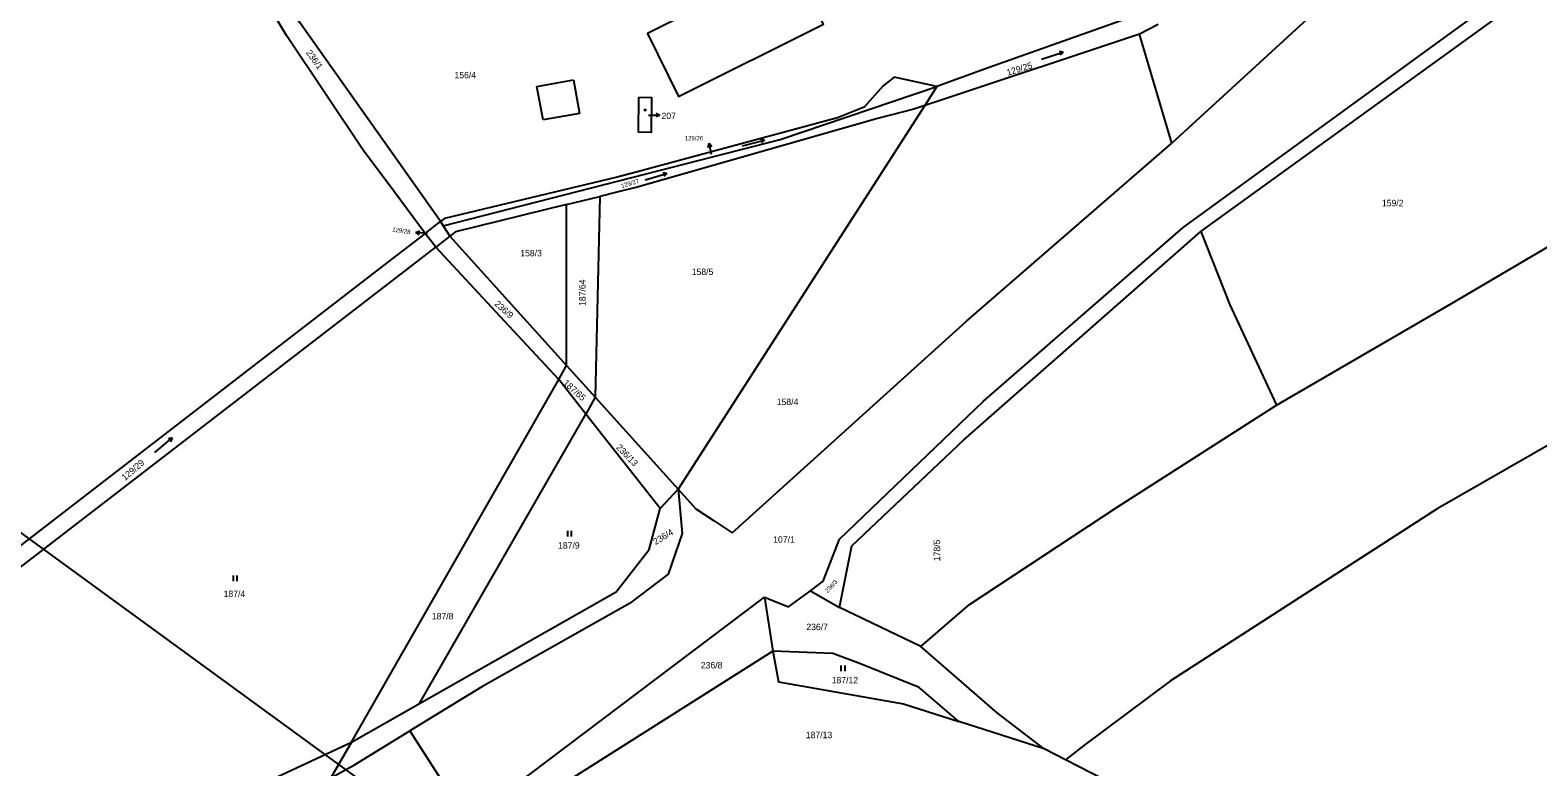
# Model space of a CAD drawing. Extents: x -670359 to -660124, y -978807 to -970072.
# Drawn here: x -662402 to -662004.8, y -971625.3 to -971431.1 of the extents above; entities that cross this region are included whole.
import ezdxf

# ---------------------------------------------------------------- set-up
doc = ezdxf.new("R2010")
doc.units = 0
for name, color, linetype in [('Hranice parcel', 7, 'Continuous'), ('Parcelní čísla', 7, 'Continuous'), ('Vnitřní kresba', 7, 'Continuous'), ('Značky budov', 7, 'Continuous'), ('Značky kultur', 7, 'Continuous')]:
    doc.layers.add(name, color=color, linetype=linetype)

# ---------------------------------------------------------------- blocks, each defined once
blk = doc.blocks.new('4.02')
at = {"layer": 'Značky budov'}
blk.add_circle((-0.01, 0), 0.175, dxfattribs=at)
blk = doc.blocks.new('8.02_4')
at = {"layer": 'Značky kultur'}
for p, q in [((-2.28, -1.92), (2.32, 1.93)), ((2.32, 1.93), (1.25, 1.69)), ((2.32, 1.93), (1.89, 0.92))]:
    blk.add_line(p, q, dxfattribs=at)
blk = doc.blocks.new('8.02_7')
at = {"layer": 'Značky kultur'}
for p, q in [((-2.83, -0.93), (2.87, 0.92)), ((2.87, 0.92), (1.79, 1.1)), ((2.87, 0.92), (2.1, 0.14))]:
    blk.add_line(p, q, dxfattribs=at)
blk = doc.blocks.new('8.02_12')
at = {"layer": 'Značky kultur'}
for p, q in [((-2.89, -0.73), (2.93, 0.72)), ((2.93, 0.72), (1.86, 0.97)), ((2.93, 0.72), (2.1, 0))]:
    blk.add_line(p, q, dxfattribs=at)
blk = doc.blocks.new('8.02_13')
at = {"layer": 'Značky kultur'}
for p, q in [((-2.86, -0.83), (2.9, 0.82)), ((2.9, 0.82), (1.82, 1.04)), ((2.9, 0.82), (2.1, 0.07))]:
    blk.add_line(p, q, dxfattribs=at)
blk = doc.blocks.new('1029_274')
at = {"layer": 'Parcelní čísla'}
for p, q in [((-0.5, 2), (0, 3)), ((0, 0), (0, 3)), ((0, 3), (0.5, 2))]:
    blk.add_line(p, q, dxfattribs=at)
blk = doc.blocks.new('3.06')
at = {"layer": 'Značky kultur'}
for p, q in [((-0.51, 0), (-0.51, 1.5)), ((0.49, 0), (0.49, 1.5))]:
    blk.add_line(p, q, dxfattribs=at)

msp = doc.modelspace()

# ---------------------------------------------------------------- linework, layer by layer
at = {"layer": 'Hranice parcel'}
for p, q in [((-664449.97, -970071.93), (-660124.07, -973226.54)), ((-662093.64, -971484.16), (-662006.91, -971421.5)), ((-662104.85, -971429.67), (-662109.78, -971432.21)), ((-662101.2, -971460.92), (-662109.78, -971432.21)), ((-662166.28, -971450.96), (-662231.31, -971552.12)), ((-662166.28, -971450.96), (-662169.24, -971451.94)), ((-662260.69, -971477.1), (-662289.92, -971484.3)), ((-662260.72, -971519.49), (-662260.69, -971477.1)), ((-662260.69, -971477.1), (-662251.9, -971474.94)), ((-662251.9, -971474.94), (-662253.16, -971527.88)), ((-662247.4, -971473.82), (-662251.9, -971474.94)), ((-662293.87, -971481.57), (-662294.28, -971481)), ((-662297.92, -971484.7), (-662293.87, -971481.57)), ((-662295.11, -971488.3), (-662297.92, -971484.7)), ((-662291.4, -971485.44), (-662295.11, -971488.3)), ((-662293.87, -971481.57), (-662293.17, -971482.67)), ((-662293.17, -971482.67), (-662291.4, -971485.44)), ((-662289.92, -971484.3), (-662291.4, -971485.44)), ((-662291.4, -971485.44), (-662260.72, -971519.49)), ((-662262.72, -971523.18), (-662260.72, -971519.49)), ((-662260.72, -971519.49), (-662253.16, -971527.88)), ((-662317.37, -971618.8), (-662262.72, -971523.18)), ((-662255.57, -971532.3), (-662262.72, -971523.18)), ((-662253.16, -971527.88), (-662255.57, -971532.3)), ((-662253.16, -971527.88), (-662231.31, -971552.12)), ((-662299.42, -971608.6), (-662255.57, -971532.3)), ((-662236.05, -971557.19), (-662255.57, -971532.3)), ((-662231.31, -971552.12), (-662236.05, -971557.19)), ((-662280.81, -971635.08), (-662208.55, -971580.53)), ((-662208.55, -971580.53), (-662206.34, -971594.76)), ((-662196.41, -971578.91), (-662188.74, -971583.27)), ((-662167.4, -971593.58), (-662188.74, -971583.27)), ((-662283.04, -971604.15), (-662302.01, -971615.82)), ((-662317.37, -971618.8), (-662299.42, -971608.6)), ((-662316.53, -971624.76), (-662302.01, -971615.82)), ((-662134.9, -971620.53), (-662157.38, -971613.31)), ((-662317.37, -971618.8), (-662322.78, -971628.13)), ((-662129.28, -971623.42), (-662134.9, -971620.53)), ((-662322.78, -971628.13), (-662316.53, -971624.76))]:
    msp.add_line(p, q, dxfattribs=at)
for points in [[(-661433.28, -971243.01), (-661557.59, -971305.11), (-661701.9, -971375.58), (-661831.06, -971446.31), (-661987.66, -971532.26), (-662031.35, -971557.26), (-662101.61, -971602.62), (-662124.46, -971619.63), (-662129.28, -971623.42)], [(-661822.45, -971261.99), (-661830.68, -971265.03), (-661863.68, -971280.61), (-661886.93, -971293.11), (-661912.11, -971308.3), (-661946.9, -971331.57), (-661983.27, -971359.52), (-662026.24, -971394.17), (-662057.15, -971420.41), (-662101.2, -971460.92)], [(-662196.41, -971578.91), (-662193.09, -971576.38), (-662188.82, -971565.31), (-662150.86, -971528.94), (-662098.27, -971483.13), (-662008, -971417.42), (-661977.36, -971384.36), (-661928.37, -971345.47), (-661860.63, -971297.88), (-661860.47, -971297.8)], [(-662294.28, -971481), (-662331.04, -971428.99), (-662343.81, -971404.49), (-662355.77, -971373.73), (-662379.27, -971301.66)], [(-662209.66, -971396.19), (-662237.17, -971409.99), (-662228.81, -971426.75), (-662239.4, -971432.04), (-662231.16, -971448.6), (-662192.99, -971429.55), (-662209.66, -971396.19)], [(-662297.92, -971484.7), (-662305.96, -971473.88), (-662314.27, -971462.71), (-662334.49, -971432.52), (-662342.84, -971418.45)], [(-662111.97, -971427.74), (-662149.37, -971440.94), (-662163.1, -971446.01)], [(-662109.78, -971432.21), (-662162.3, -971449.64), (-662166.28, -971450.96)], [(-662163.1, -971446.01), (-662174.34, -971443.55), (-662177.28, -971445.81), (-662182.3, -971451.38), (-662189.31, -971454.22), (-662242.31, -971468.56), (-662247.35, -971469.91), (-662292.81, -971480.76), (-662293.87, -971481.57)], [(-662293.17, -971482.67), (-662204.37, -971459.94), (-662163.1, -971446.01)], [(-662238.34, -971448.8), (-662238.36, -971458.08), (-662241.73, -971458.04), (-662241.66, -971448.84), (-662238.34, -971448.8)], [(-662163.1, -971446.01), (-662165.69, -971450.04), (-662166.28, -971450.96)], [(-662169.24, -971451.94), (-662178.45, -971454.3), (-662242.12, -971472.51), (-662247.4, -971473.82)], [(-662231.31, -971552.12), (-662226.64, -971557.25), (-662221.79, -971560.46), (-662217.03, -971563.6), (-662198.22, -971546.59), (-662155.3, -971507.79), (-662101.2, -971460.92)], [(-662297.92, -971484.7), (-662306.49, -971491.31), (-662436.14, -971591.26), (-662441.35, -971595.28), (-662445.35, -971598.37), (-662453.45, -971604.61), (-662454.94, -971605.76), (-662452.39, -971609.5)], [(-662188.74, -971583.27), (-662185.51, -971567.05), (-662156, -971539.05), (-662093.64, -971484.16)], [(-662093.64, -971484.16), (-662085.99, -971503.48), (-662073.68, -971529.94)], [(-662073.68, -971529.94), (-662026.5, -971502.57), (-661991.31, -971481.85)], [(-662452.39, -971609.5), (-662451.45, -971608.77), (-662443.35, -971602.53), (-662433.69, -971595.09), (-662302.4, -971493.92), (-662295.11, -971488.3)], [(-662262.72, -971523.18), (-662278.14, -971506.58), (-662295.11, -971488.3)], [(-662167.4, -971593.58), (-662154.56, -971582.53), (-662115.34, -971556.63), (-662073.68, -971529.94)], [(-662231.31, -971552.12), (-662230.27, -971563.74), (-662233.93, -971574.53), (-662244.13, -971582.23), (-662283.04, -971604.15)], [(-662299.42, -971608.6), (-662247.59, -971579.14), (-662238.93, -971567.98), (-662236.05, -971557.19)], [(-662208.55, -971580.53), (-662202.21, -971583.13), (-662196.41, -971578.91)], [(-662206.34, -971594.76), (-662259.74, -971628.59), (-662265.92, -971632.83)], [(-662157.38, -971613.31), (-662167.81, -971604.35), (-662183.22, -971598.13), (-662190.55, -971595.39), (-662206.34, -971594.76)], [(-662206.34, -971594.76), (-662204.89, -971602.85), (-662171.88, -971608.66), (-662157.38, -971613.31)], [(-662134.9, -971620.53), (-662147.25, -971611.06), (-662167.4, -971593.58)], [(-662302.01, -971615.82), (-662295.37, -971626.1), (-662286.28, -971640.18)], [(-662378.56, -971643.54), (-662367.8, -971636.85), (-662357.61, -971632.99), (-662341.07, -971629.83), (-662317.37, -971618.8)], [(-662022.47, -971723.71), (-662037.36, -971699.64), (-662056.77, -971673.81), (-662083.87, -971653.68), (-662108.86, -971633.91), (-662129.28, -971623.42)]]:
    msp.add_lwpolyline(points, dxfattribs=at)
at = {"layer": 'Vnitřní kresba'}
for p, q in [((-662268.49, -971445.94), (-662258.87, -971444.25)), ((-662258.87, -971444.25), (-662257.28, -971453.1)), ((-662266.87, -971454.72), (-662268.49, -971445.94)), ((-662257.28, -971453.1), (-662266.87, -971454.72))]:
    msp.add_line(p, q, dxfattribs=at)

# ---------------------------------------------------------------- block references
at = {"layer": 'Parcelní čísla'}
for p, rotation in [((-662239.07, -971453.49), -90.00000000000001), ((-662222.47, -971463.87), 11.79251693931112), ((-662297.35, -971484.67), 86.49200502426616)]:
    msp.add_blockref('1029_274', p, dxfattribs=dict(at, rotation=rotation))
at = {"layer": 'Značky budov'}
msp.add_blockref('4.02', (-662239.96, -971452.18), dxfattribs=at)
at = {"layer": 'Značky kultur'}
for name, p in [('8.02_7', (-662132.71, -971437.86)), ('8.02_12', (-662211.44, -971460.85)), ('8.02_13', (-662237.14, -971469.75)), ('8.02_4', (-662366.87, -971540.51)), ('3.06', (-662259.87, -971564.55)), ('3.06', (-662347.94, -971576.32)), ('3.06', (-662187.81, -971600.03))]:
    msp.add_blockref(name, p, dxfattribs=at)

# ---------------------------------------------------------------- texts
at = {"layer": 'Parcelní čísla'}
for s, height, rotation, p in [('236/1', 1.7, 305.8616, (-662329.42, -971437.05)), ('129/25', 1.7, 17, (-662144.45, -971443.16)), ('129/27', 1.14, 17, (-662246.11, -971472.76)), ('129/28', 1.14, 351.8212, (-662306.66, -971484.19)), ('187/64', 1.7, 90, (-662255.67, -971503.8)), ('236/9', 1.7, 318, (-662279.83, -971503.47)), ('187/65', 1.7, 318, (-662261.73, -971524.33)), ('236/13', 1.7, 314, (-662247.75, -971541.22)), ('129/29', 1.7, 41, (-662376.98, -971549.95)), ('236/4', 1.7, 30.8224, (-662237.25, -971566.84)), ('178/5', 1.7, 90, (-662162.26, -971571.07)), ('236/3', 1.14, 47, (-662191.91, -971579.51))]:
    msp.add_text(s, height=height, rotation=rotation, dxfattribs=at).set_placement(p)
for s, height, p in [('156/4', 1.7, (-662290.2, -971443.82)), ('207', 1.7, (-662235.67, -971454.56)), ('129/26', 1.14, (-662229.53, -971460.17)), ('159/2', 1.7, (-662045.89, -971477.54)), ('158/3', 1.7, (-662272.87, -971490.74)), ('158/5', 1.7, (-662227.71, -971495.65)), ('158/4', 1.7, (-662205.31, -971529.93)), ('107/1', 1.7, (-662206.24, -971566.21)), ('187/9', 1.7, (-662262.91, -971567.76)), ('187/4', 1.7, (-662351.02, -971580.54)), ('187/8', 1.7, (-662296.17, -971586.42)), ('236/7', 1.7, (-662197.52, -971589.25)), ('236/8', 1.7, (-662225.31, -971599.34)), ('187/12', 1.7, (-662190.84, -971603.27)), ('187/13', 1.7, (-662197.65, -971617.72))]:
    msp.add_text(s, height=height, dxfattribs=at).set_placement(p)

doc.saveas('drawing.dxf')
